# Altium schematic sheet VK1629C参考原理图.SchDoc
size A3
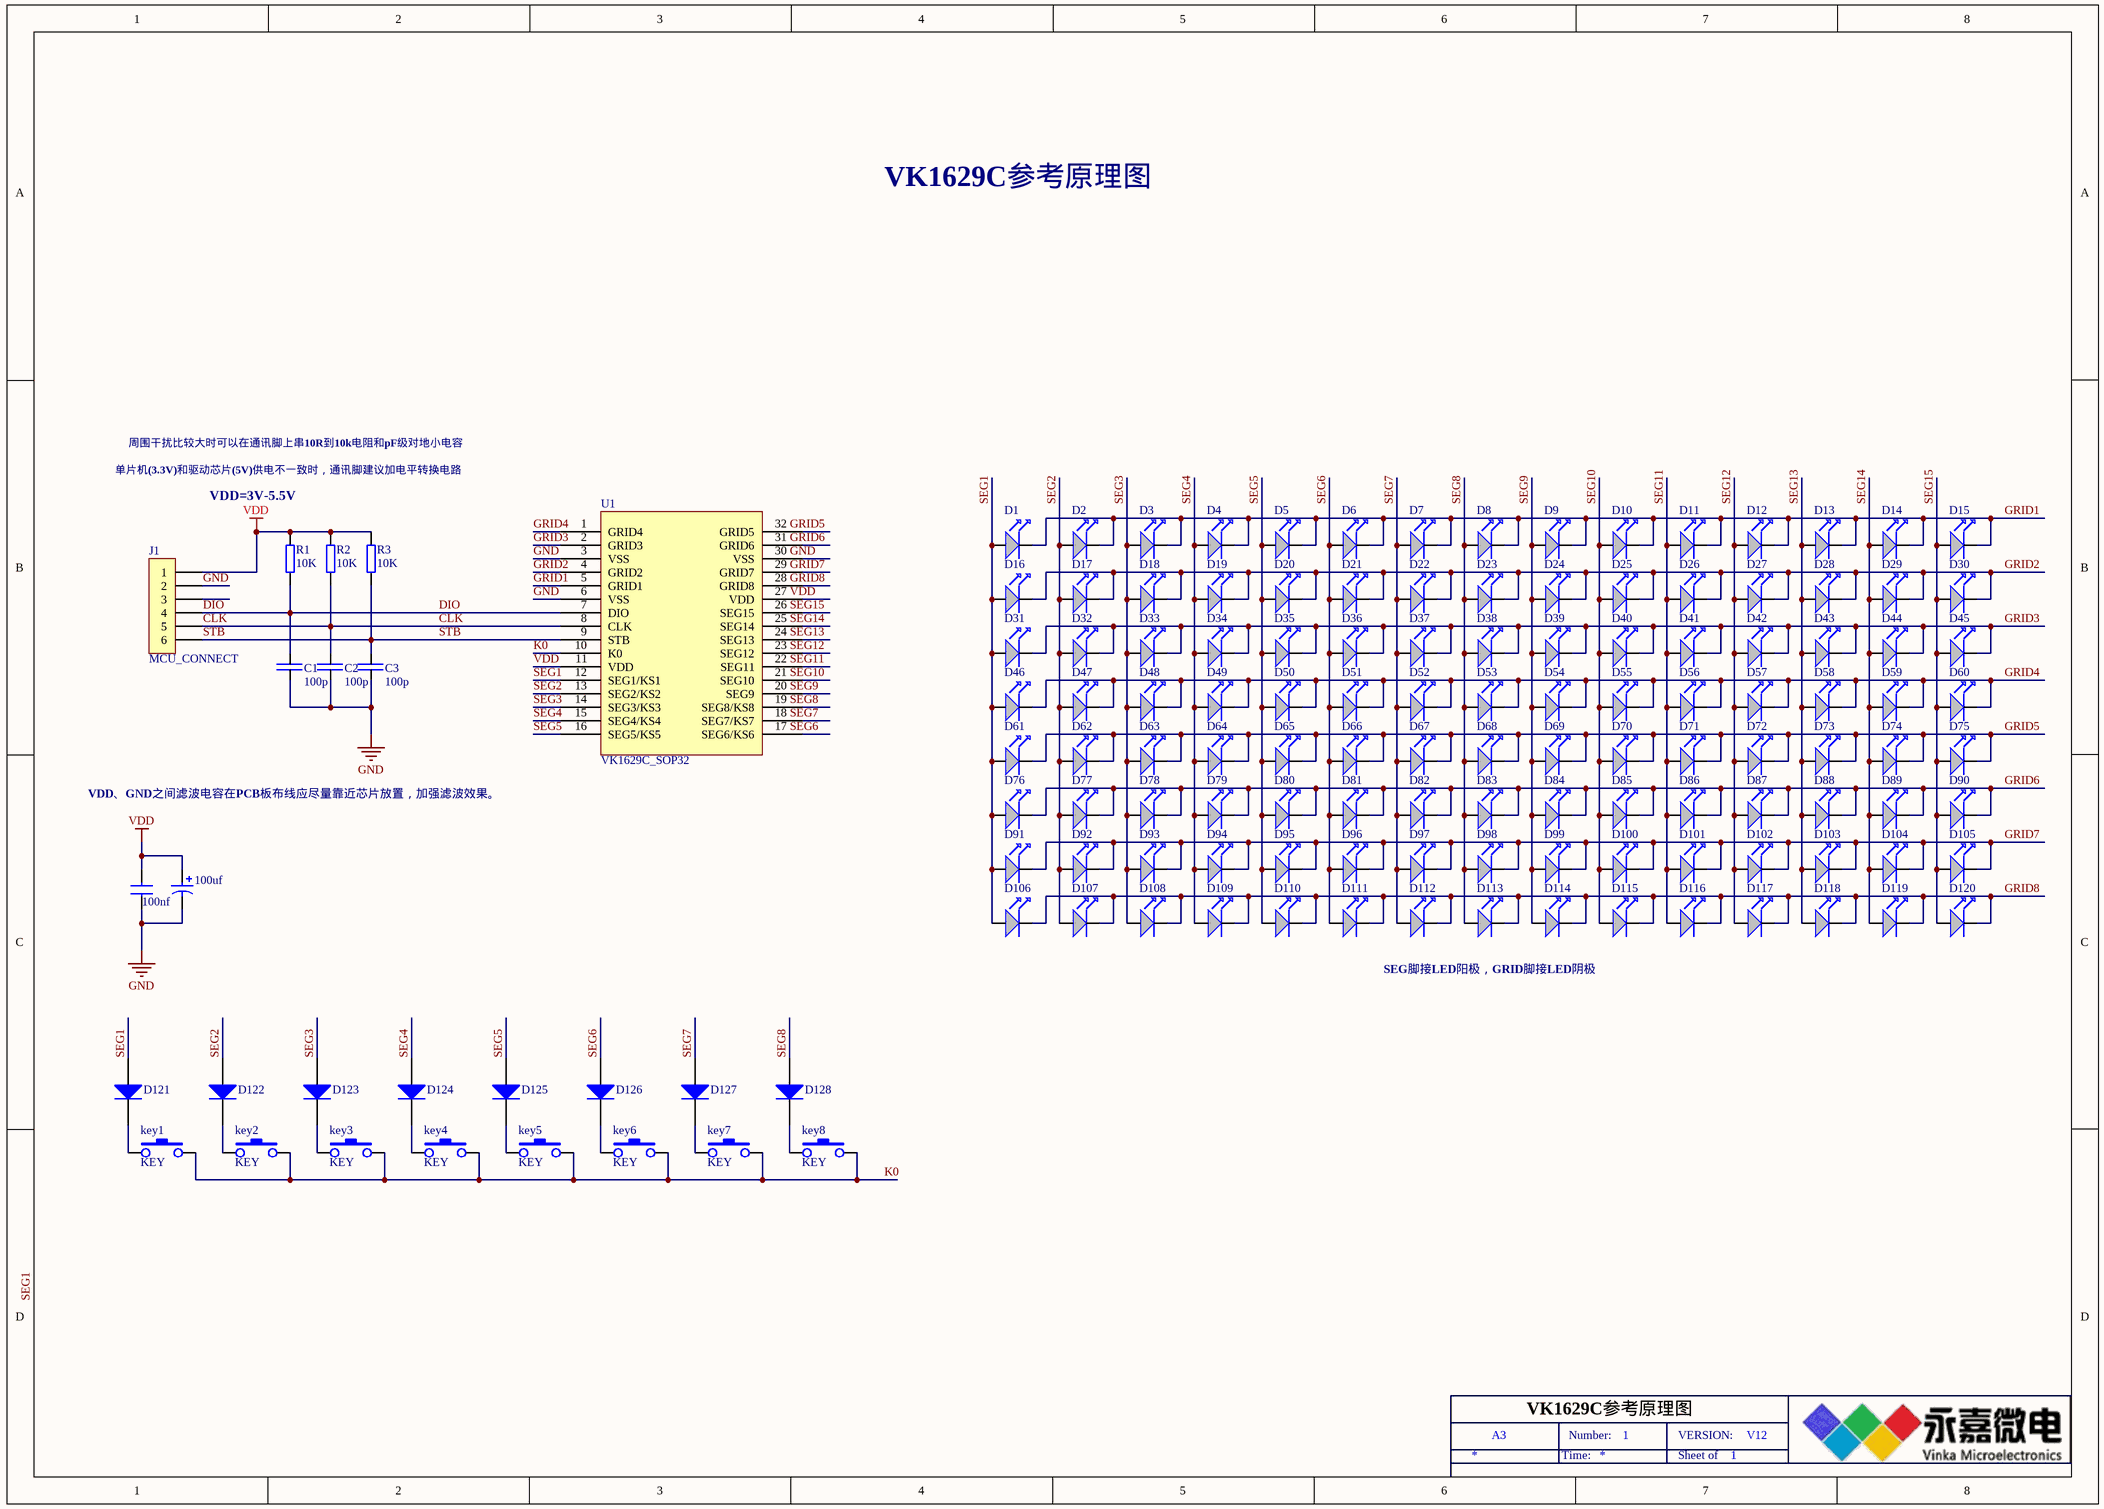
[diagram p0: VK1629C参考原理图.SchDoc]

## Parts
100nf  CAP  (value not drawn)
100uf  CAP2  (value not drawn)
C1  100p  [C0603]
C2  100p  [C0603]
C3  100p  [C0603]
D1  (no value)  [1206-LED]
D2  (no value)  [1206-LED]
D3  (no value)  [1206-LED]
D4  (no value)  [1206-LED]
D5  (no value)  [1206-LED]
D6  (no value)  [1206-LED]
D7  (no value)  [1206-LED]
D8  (no value)  [1206-LED]
D9  (no value)  [1206-LED]
D10  (no value)  [1206-LED]
D11  (no value)  [1206-LED]
D12  (no value)  [1206-LED]
D13  (no value)  [1206-LED]
D14  (no value)  [1206-LED]
D15  (no value)  [1206-LED]
D16  (no value)  [1206-LED]
D17  (no value)  [1206-LED]
D18  (no value)  [1206-LED]
D19  (no value)  [1206-LED]
D20  (no value)  [1206-LED]
D21  (no value)  [1206-LED]
D22  (no value)  [1206-LED]
D23  (no value)  [1206-LED]
D24  (no value)  [1206-LED]
D25  (no value)  [1206-LED]
D26  (no value)  [1206-LED]
D27  (no value)  [1206-LED]
D28  (no value)  [1206-LED]
D29  (no value)  [1206-LED]
D30  (no value)  [1206-LED]
D31  (no value)  [1206-LED]
D32  (no value)  [1206-LED]
D33  (no value)  [1206-LED]
D34  (no value)  [1206-LED]
D35  (no value)  [1206-LED]
D36  (no value)  [1206-LED]
D37  (no value)  [1206-LED]
D38  (no value)  [1206-LED]
D39  (no value)  [1206-LED]
D40  (no value)  [1206-LED]
D41  (no value)  [1206-LED]
D42  (no value)  [1206-LED]
D43  (no value)  [1206-LED]
D44  (no value)  [1206-LED]
D45  (no value)  [1206-LED]
D46  (no value)  [1206-LED]
D47  (no value)  [1206-LED]
D48  (no value)  [1206-LED]
D49  (no value)  [1206-LED]
D50  (no value)  [1206-LED]
D51  (no value)  [1206-LED]
D52  (no value)  [1206-LED]
D53  (no value)  [1206-LED]
D54  (no value)  [1206-LED]
D55  (no value)  [1206-LED]
D56  (no value)  [1206-LED]
D57  (no value)  [1206-LED]
D58  (no value)  [1206-LED]
D59  (no value)  [1206-LED]
D60  (no value)  [1206-LED]
D61  (no value)  [1206-LED]
D62  (no value)  [1206-LED]
D63  (no value)  [1206-LED]
D64  (no value)  [1206-LED]
D65  (no value)  [1206-LED]
D66  (no value)  [1206-LED]
D67  (no value)  [1206-LED]
D68  (no value)  [1206-LED]
D69  (no value)  [1206-LED]
D70  (no value)  [1206-LED]
D71  (no value)  [1206-LED]
D72  (no value)  [1206-LED]
D73  (no value)  [1206-LED]
D74  (no value)  [1206-LED]
D75  (no value)  [1206-LED]
D76  (no value)  [1206-LED]
D77  (no value)  [1206-LED]
D78  (no value)  [1206-LED]
D79  (no value)  [1206-LED]
D80  (no value)  [1206-LED]
D81  (no value)  [1206-LED]
D82  (no value)  [1206-LED]
D83  (no value)  [1206-LED]
D84  (no value)  [1206-LED]
D85  (no value)  [1206-LED]
D86  (no value)  [1206-LED]
D87  (no value)  [1206-LED]
D88  (no value)  [1206-LED]
D89  (no value)  [1206-LED]
D90  (no value)  [1206-LED]
D91  (no value)  [1206-LED]
D92  (no value)  [1206-LED]
D93  (no value)  [1206-LED]
D94  (no value)  [1206-LED]
D95  (no value)  [1206-LED]
D96  (no value)  [1206-LED]
D97  (no value)  [1206-LED]
D98  (no value)  [1206-LED]
D99  (no value)  [1206-LED]
D100  (no value)  [1206-LED]
D101  (no value)  [1206-LED]
D102  (no value)  [1206-LED]
D103  (no value)  [1206-LED]
D104  (no value)  [1206-LED]
D105  (no value)  [1206-LED]
D106  (no value)  [1206-LED]
D107  (no value)  [1206-LED]
D108  (no value)  [1206-LED]
D109  (no value)  [1206-LED]
D110  (no value)  [1206-LED]
D111  (no value)  [1206-LED]
D112  (no value)  [1206-LED]
D113  (no value)  [1206-LED]
D114  (no value)  [1206-LED]
D115  (no value)  [1206-LED]
D116  (no value)  [1206-LED]
D117  (no value)  [1206-LED]
D118  (no value)  [1206-LED]
D119  (no value)  [1206-LED]
D120  (no value)  [1206-LED]
D121  Diode 1N4003  [DO-41]  (value not drawn)
D122  Diode 1N4003  [DO-41]  (value not drawn)
D123  Diode 1N4003  [DO-41]  (value not drawn)
D124  Diode 1N4003  [DO-41]  (value not drawn)
D125  Diode 1N4003  [DO-41]  (value not drawn)
D126  Diode 1N4003  [DO-41]  (value not drawn)
D127  Diode 1N4003  [DO-41]  (value not drawn)
D128  Diode 1N4003  [DO-41]  (value not drawn)
J1  MCU_CONNECT
key1  KEY  [AN12]
key2  KEY  [AN12]
key3  KEY  [AN12]
key4  KEY  [AN12]
key5  KEY  [AN12]
key6  KEY  [AN12]
key7  KEY  [AN12]
key8  KEY  [AN12]
R1  10K  [0603-R]
R2  10K  [0603-R]
R3  10K  [0603-R]
U1  VK1629C_SOP32

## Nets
GND: 100nf.2 100uf.2 C1.2 C2.2 C3.2 J1.2 U1.3(VSS) U1.6(VSS)
VDD: 100nf.1 100uf.1 J1.1 R1.1 R2.1 R3.1 U1.11(VDD)
CLK: C2.1 J1.5 R2.2 U1.8(CLK)
DIO: C1.1 J1.4 R1.2 U1.7(DIO)
GRID1: D1.2 D2.2 D3.2 D4.2 D5.2 D6.2 D7.2 D8.2 D9.2 D10.2 D11.2 D12.2 D13.2 D14.2 D15.2 U1.5(GRID1)
GRID2: D16.2 D17.2 D18.2 D19.2 D20.2 D21.2 D22.2 D23.2 D24.2 D25.2 D26.2 D27.2 D28.2 D29.2 D30.2 U1.4(GRID2)
GRID3: D31.2 D32.2 D33.2 D34.2 D35.2 D36.2 D37.2 D38.2 D39.2 D40.2 D41.2 D42.2 D43.2 D44.2 D45.2 U1.2(GRID3)
GRID4: D46.2 D47.2 D48.2 D49.2 D50.2 D51.2 D52.2 D53.2 D54.2 D55.2 D56.2 D57.2 D58.2 D59.2 D60.2 U1.1(GRID4)
GRID5: D61.2 D62.2 D63.2 D64.2 D65.2 D66.2 D67.2 D68.2 D69.2 D70.2 D71.2 D72.2 D73.2 D74.2 D75.2
GRID6: D76.2 D77.2 D78.2 D79.2 D80.2 D81.2 D82.2 D83.2 D84.2 D85.2 D86.2 D87.2 D88.2 D89.2 D90.2
GRID7: D91.2 D92.2 D93.2 D94.2 D95.2 D96.2 D97.2 D98.2 D99.2 D100.2 D101.2 D102.2 D103.2 D104.2 D105.2
GRID8: D106.2 D107.2 D108.2 D109.2 D110.2 D111.2 D112.2 D113.2 D114.2 D115.2 D116.2 D117.2 D118.2 D119.2 D120.2
K0: key1.2 key2.2 key3.2 key4.2 key5.2 key6.2 key7.2 key8.2 U1.10(K0)
SEG1: D1.1 D16.1 D31.1 D46.1 D61.1 D76.1 D91.1 D106.1 D121.1(A) U1.12(SEG1/KS1)
SEG2: D2.1 D17.1 D32.1 D47.1 D62.1 D77.1 D92.1 D107.1 D122.1(A) U1.13(SEG2/KS2)
SEG3: D3.1 D18.1 D33.1 D48.1 D63.1 D78.1 D93.1 D108.1 D123.1(A) U1.14(SEG3/KS3)
SEG4: D4.1 D19.1 D34.1 D49.1 D64.1 D79.1 D94.1 D109.1 D124.1(A) U1.15(SEG4/KS4)
SEG5: D5.1 D20.1 D35.1 D50.1 D65.1 D80.1 D95.1 D110.1 D125.1(A) U1.16(SEG5/KS5)
SEG6: D6.1 D21.1 D36.1 D51.1 D66.1 D81.1 D96.1 D111.1 D126.1(A)
SEG7: D7.1 D22.1 D37.1 D52.1 D67.1 D82.1 D97.1 D112.1 D127.1(A)
SEG8: D8.1 D23.1 D38.1 D53.1 D68.1 D83.1 D98.1 D113.1 D128.1(A)
SEG9: D9.1 D24.1 D39.1 D54.1 D69.1 D84.1 D99.1 D114.1
SEG10: D10.1 D25.1 D40.1 D55.1 D70.1 D85.1 D100.1 D115.1
SEG11: D11.1 D26.1 D41.1 D56.1 D71.1 D86.1 D101.1 D116.1
SEG12: D12.1 D27.1 D42.1 D57.1 D72.1 D87.1 D102.1 D117.1
SEG13: D13.1 D28.1 D43.1 D58.1 D73.1 D88.1 D103.1 D118.1
SEG14: D14.1 D29.1 D44.1 D59.1 D74.1 D89.1 D104.1 D119.1
SEG15: D15.1 D30.1 D45.1 D60.1 D75.1 D90.1 D105.1 D120.1
STB: C3.1 J1.6 R3.2 U1.9(STB)
NetD121_2: D121.2(K) key1.1
NetD122_2: D122.2(K) key2.1
NetD123_2: D123.2(K) key3.1
NetD124_2: D124.2(K) key4.1
NetD125_2: D125.2(K) key5.1
NetD126_2: D126.2(K) key6.1
NetD127_2: D127.2(K) key7.1
NetD128_2: D128.2(K) key8.1

Not connected (* = marked no-connect by the designer): J1 3; U1 17(SEG6/KS6) 18(SEG7/KS7) 19(SEG8/KS8) 20(SEG9) 21(SEG10) 22(SEG11) 23(SEG12) 24(SEG13) 25(SEG14) 26(SEG15) 27(VDD) 28(GRID8) 29(GRID7) 30(VSS) 31(GRID6) 32(GRID5)

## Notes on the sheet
- VK1629C参考原理图
- 周围干扰比较大时可以在通讯脚上串10R到10k电阻和pF级对地小电容
- 单片机(3.3V)和驱动芯片(5V)供电不一致时，通讯脚建议加电平转换电路
- VDD=3V-5.5V
- VDD、GND之间滤波电容在PCB板布线应尽量靠近芯片放置，加强滤波效果。
- SEG脚接LED阳极，GRID脚接LED阴极
- A3
- Time:
- Number:
- 1
- Sheet of
- VERSION:
- V12
- Labels drawn without touching a wire or pin: GND, GRID5, GRID6, GRID7, GRID8, SEG1, SEG6, SEG7, SEG8, SEG9, SEG10, SEG11, SEG12, SEG13, SEG14, SEG15, VDD

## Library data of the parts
100nf = CAP: Capacitor
100uf = CAP2: Bi-Polar Capacitor
C1-C3 = CAP: 分类: 电容; 参数: 20%,50V,X5R
D1-D120 = LED: Text Field1: 30; Text Field2: 20
D121-D128 = Diode 1N4003: 1 Amp General Purpose Rectifier
J1 = CON6: Connector
R1-R3 = RES: Resistor
U1 = VK1629C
